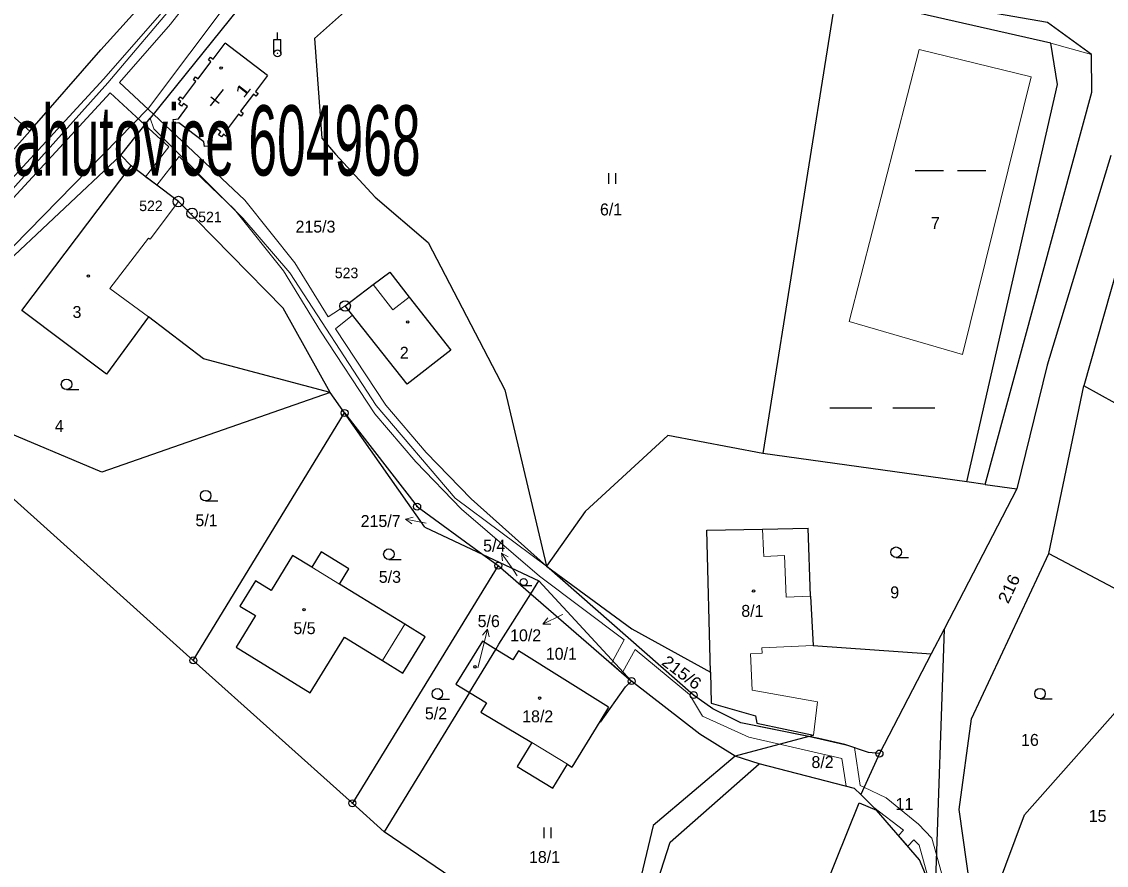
# Model space of a CAD drawing. Extents: x -504006 to -501322, y -1128098 to -1124665.
# Drawn here: x -502824.9 to -502670.2, y -1126824.4 to -1126704.2 of the extents above; entities that cross this region are included whole.
import ezdxf
from ezdxf.enums import TextEntityAlignment as Align

# ---------------------------------------------------------------- set-up
doc = ezdxf.new("R2010")
doc.units = 0
doc.header["$LTSCALE"] = 0.68
for name, color, linetype, lineweight in [('1', 7, 'Continuous', 25), ('13', 7, 'Continuous', 13), ('3', 7, 'Continuous', 25), ('4', 7, 'Continuous', 13), ('5', 7, 'Continuous', 25), ('6', 7, 'Continuous', 25), ('7', 7, 'Continuous', 13), ('8', 7, 'Continuous', 25)]:
    doc.layers.add(name, color=color, linetype=linetype, lineweight=lineweight)
doc.layers.add('2', color=7, linetype='Continuous')

msp = doc.modelspace()

# ---------------------------------------------------------------- linework, layer by layer
at = {"layer": '1'}
for p, q in [((-502774.86, -1126678.46), (-502806.52, -1126717.92)), ((-502813.58, -1126708.19), (-502802.89, -1126696.3)), ((-502708.77, -1126700.27), (-502719.18, -1126765.7)), ((-502678.13, -1126707.24), (-502708.77, -1126700.27)), ((-502678.61, -1126704.28), (-502706.62, -1126699.4)), ((-502776.7, -1126700.81), (-502783.12, -1126706.55)), ((-502672.35, -1126708.85), (-502678.61, -1126704.28)), ((-502783.12, -1126706.55), (-502782.07, -1126720.79)), ((-502823.71, -1126719.75), (-502813.58, -1126708.19)), ((-502797.58, -1126709.49), (-502795.85, -1126707.23)), ((-502789.83, -1126711.86), (-502795.85, -1126707.23)), ((-502677.17, -1126713.1), (-502678.13, -1126707.24)), ((-502798.24, -1126709.62), (-502797.94, -1126709.21)), ((-502797.88, -1126709.89), (-502798.24, -1126709.62)), ((-502797.94, -1126709.21), (-502797.58, -1126709.49)), ((-502672.3, -1126714.21), (-502672.35, -1126708.85)), ((-502799.72, -1126712.31), (-502797.88, -1126709.89)), ((-502801.87, -1126715.14), (-502800.03, -1126712.71)), ((-502800.38, -1126712.44), (-502800.07, -1126712.05)), ((-502800.03, -1126712.71), (-502800.38, -1126712.44)), ((-502800.07, -1126712.05), (-502799.72, -1126712.31)), ((-502789.83, -1126711.86), (-502791.52, -1126714.11)), ((-502791.52, -1126714.11), (-502791.14, -1126714.4)), ((-502791.14, -1126714.4), (-502791.46, -1126714.79)), ((-502690.12, -1126769.75), (-502677.17, -1126713.1)), ((-502687.5, -1126770.11), (-502672.3, -1126714.21)), ((-502802.53, -1126715.27), (-502802.23, -1126714.86)), ((-502802.18, -1126715.54), (-502802.53, -1126715.27)), ((-502802.47, -1126715.92), (-502802.18, -1126715.54)), ((-502802.07, -1126716.22), (-502802.47, -1126715.92)), ((-502802.23, -1126714.86), (-502801.87, -1126715.14)), ((-502801.78, -1126715.84), (-502802.07, -1126716.22)), ((-502801.22, -1126716.26), (-502801.78, -1126715.84)), ((-502791.82, -1126714.52), (-502793.64, -1126716.93)), ((-502791.46, -1126714.79), (-502791.82, -1126714.52)), ((-502802.51, -1126718.02), (-502801.22, -1126716.26)), ((-502793.94, -1126717.34), (-502795.8, -1126719.81)), ((-502793.57, -1126717.62), (-502793.94, -1126717.34)), ((-502793.64, -1126716.93), (-502793.28, -1126717.21)), ((-502793.28, -1126717.21), (-502793.57, -1126717.62)), ((-502810.72, -1126723.17), (-502806.52, -1126717.92)), ((-502803.25, -1126718.11), (-502802.51, -1126718.02)), ((-502803.17, -1126718.69), (-502803.25, -1126718.11)), ((-502802.46, -1126718.59), (-502803.17, -1126718.69)), ((-502798.91, -1126721.27), (-502802.46, -1126718.59)), ((-502826.25, -1126722.68), (-502823.71, -1126719.75)), ((-502797.03, -1126719.45), (-502798.32, -1126721.19)), ((-502796.48, -1126719.87), (-502797.03, -1126719.45)), ((-502796.79, -1126720.29), (-502796.48, -1126719.87)), ((-502796.38, -1126720.59), (-502796.79, -1126720.29)), ((-502796.1, -1126720.21), (-502796.38, -1126720.59)), ((-502795.74, -1126720.48), (-502796.1, -1126720.21)), ((-502795.8, -1126719.81), (-502795.43, -1126720.08)), ((-502795.43, -1126720.08), (-502795.74, -1126720.48)), ((-502798.81, -1126721.95), (-502798.91, -1126721.27)), ((-502798.25, -1126721.9), (-502798.81, -1126721.95)), ((-502798.32, -1126721.19), (-502798.25, -1126721.9)), ((-502782.07, -1126720.79), (-502780.1, -1126723.05)), ((-502663.74, -1126721.77), (-502673.41, -1126756.05)), ((-502836.98, -1126747.85), (-502810.72, -1126723.17)), ((-502809.26, -1126724.71), (-502810.72, -1126723.17)), ((-502780.1, -1126723.05), (-502774.45, -1126729.16)), ((-502669.57, -1126723.24), (-502678.64, -1126753.11)), ((-502824.82, -1126745.34), (-502809.26, -1126724.71)), ((-502802.52, -1126729.8), (-502809.26, -1126724.71)), ((-502787.59, -1126744.98), (-502802.52, -1126729.8)), ((-502774.45, -1126729.16), (-502766.91, -1126735.65)), ((-502766.91, -1126735.65), (-502755.98, -1126756.66)), ((-502774.77, -1126741.64), (-502772.37, -1126739.86)), ((-502772.37, -1126739.86), (-502769.6, -1126743.42)), ((-502778.75, -1126744.69), (-502774.77, -1126741.64)), ((-502769.6, -1126743.42), (-502763.67, -1126750.97)), ((-502812.78, -1126754.4), (-502824.82, -1126745.34)), ((-502780.87, -1126757.03), (-502787.59, -1126744.98)), ((-502769.88, -1126755.81), (-502778.75, -1126744.69)), ((-502806.76, -1126746.24), (-502812.78, -1126754.4)), ((-502798.94, -1126752.2), (-502806.76, -1126746.24)), ((-502763.67, -1126750.97), (-502769.88, -1126755.81)), ((-502780.87, -1126757.03), (-502798.94, -1126752.2)), ((-502678.64, -1126753.11), (-502682.97, -1126770.74)), ((-502813.43, -1126768.36), (-502845.16, -1126755)), ((-502800.39, -1126795.2), (-502845.16, -1126755)), ((-502678.41, -1126779.95), (-502673.41, -1126756.05)), ((-502632.62, -1126778.97), (-502673.41, -1126756.05)), ((-502780.87, -1126757.03), (-502813.43, -1126768.36)), ((-502778.82, -1126759.94), (-502780.87, -1126757.03)), ((-502755.98, -1126756.66), (-502750.05, -1126781.76)), ((-502800.39, -1126795.2), (-502778.82, -1126759.94)), ((-502778.82, -1126759.94), (-502768.48, -1126773.29)), ((-502767.37, -1126776.23), (-502778.82, -1126759.94)), ((-502732.75, -1126763.16), (-502744.53, -1126773.97)), ((-502719.18, -1126765.7), (-502732.75, -1126763.16)), ((-502690.12, -1126769.75), (-502719.18, -1126765.7)), ((-502687.5, -1126770.11), (-502690.12, -1126769.75)), ((-502682.97, -1126770.74), (-502693.34, -1126790.73)), ((-502687.5, -1126770.11), (-502682.97, -1126770.74)), ((-502768.48, -1126773.29), (-502759.11, -1126780.1)), ((-502744.53, -1126773.97), (-502750.05, -1126781.76)), ((-502767.37, -1126776.23), (-502759.11, -1126780.1)), ((-502727.18, -1126776.65), (-502719.22, -1126776.48)), ((-502726.66, -1126796.86), (-502727.18, -1126776.65)), ((-502719.22, -1126776.48), (-502712.72, -1126776.34)), ((-502712.39, -1126786.06), (-502712.72, -1126776.34)), ((-502786.26, -1126780.23), (-502789.3, -1126785.22)), ((-502783.51, -1126781.9), (-502786.26, -1126780.23)), ((-502782.18, -1126779.72), (-502783.51, -1126781.9)), ((-502778.21, -1126782.16), (-502782.18, -1126779.72)), ((-502759.11, -1126780.1), (-502751.13, -1126783.84)), ((-502759.11, -1126780.1), (-502756.91, -1126781.7)), ((-502689.46, -1126803.51), (-502678.41, -1126779.95)), ((-502678.41, -1126779.95), (-502641.75, -1126799.38)), ((-502779.53, -1126784.33), (-502778.21, -1126782.16)), ((-502756.91, -1126781.7), (-502777.71, -1126815.57)), ((-502756.91, -1126781.7), (-502752.29, -1126785.7)), ((-502729.06, -1126800.14), (-502750.05, -1126781.76)), ((-502750.05, -1126781.76), (-502737.86, -1126790.7)), ((-502789.3, -1126785.22), (-502791.53, -1126783.85)), ((-502752.29, -1126785.7), (-502751.13, -1126783.84)), ((-502737.9, -1126798.15), (-502751.13, -1126783.84)), ((-502770.22, -1126790.02), (-502779.53, -1126784.33)), ((-502756.81, -1126792.91), (-502752.29, -1126785.7)), ((-502752.29, -1126785.7), (-502737.9, -1126798.15)), ((-502712.39, -1126786.06), (-502712.03, -1126793.06)), ((-502791.51, -1126788.81), (-502794.29, -1126793.34)), ((-502767.35, -1126791.85), (-502770.22, -1126790.02)), ((-502737.86, -1126790.7), (-502726.66, -1126796.86)), ((-502693.34, -1126790.73), (-502695.19, -1126794.28)), ((-502693.34, -1126790.73), (-502694.72, -1126830.65)), ((-502783.73, -1126799.81), (-502778.84, -1126791.87)), ((-502778.84, -1126791.87), (-502773.4, -1126795.24)), ((-502770.52, -1126797.04), (-502767.35, -1126791.85)), ((-502759.17, -1126792.47), (-502762.94, -1126798.59)), ((-502757.26, -1126793.65), (-502759.17, -1126792.47)), ((-502757.26, -1126793.65), (-502756.81, -1126792.91)), ((-502712.03, -1126793.06), (-502695.19, -1126794.28)), ((-502794.29, -1126793.34), (-502783.73, -1126799.81)), ((-502761.02, -1126799.77), (-502757.26, -1126793.65)), ((-502754.84, -1126795.14), (-502757.26, -1126793.65)), ((-502754.02, -1126793.83), (-502754.84, -1126795.14)), ((-502741.18, -1126801.89), (-502754.02, -1126793.83)), ((-502695.19, -1126794.28), (-502702.56, -1126808.48)), ((-502777.71, -1126815.57), (-502800.39, -1126795.2)), ((-502773.4, -1126795.24), (-502770.52, -1126797.04)), ((-502726.66, -1126796.86), (-502726.54, -1126801.31)), ((-502681.9, -1126817.21), (-502664.13, -1126797.18)), ((-502762.94, -1126798.59), (-502761.02, -1126799.77)), ((-502742.33, -1126804.02), (-502738.77, -1126798.95)), ((-502737.9, -1126798.15), (-502738.77, -1126798.95)), ((-502728.16, -1126805.7), (-502737.9, -1126798.15)), ((-502761.02, -1126799.77), (-502773.2, -1126819.62)), ((-502761.02, -1126799.77), (-502758.61, -1126801.26)), ((-502726.33, -1126802.1), (-502729.06, -1126800.14)), ((-502758.61, -1126801.26), (-502759.41, -1126802.56)), ((-502759.41, -1126802.56), (-502752.12, -1126806.91)), ((-502741.18, -1126801.89), (-502742.44, -1126803.93)), ((-502726.54, -1126801.31), (-502720.23, -1126803.09)), ((-502722.34, -1126804.09), (-502726.33, -1126802.1)), ((-502742.44, -1126803.93), (-502746.41, -1126810.4)), ((-502742.44, -1126803.93), (-502742.33, -1126804.02)), ((-502712.63, -1126806.04), (-502722.34, -1126804.09)), ((-502720.23, -1126803.09), (-502720.04, -1126804.13)), ((-502720.04, -1126804.13), (-502711.99, -1126805.87)), ((-502691.21, -1126816.43), (-502689.46, -1126803.51)), ((-502752.12, -1126806.91), (-502754.21, -1126810.33)), ((-502723.14, -1126808.83), (-502728.16, -1126805.7)), ((-502712.63, -1126806.04), (-502723.14, -1126808.83)), ((-502712.63, -1126806.04), (-502711.99, -1126805.87)), ((-502711.23, -1126806.32), (-502712.63, -1126806.04)), ((-502707.51, -1126807.18), (-502711.23, -1126806.32)), ((-502704.14, -1126808.31), (-502707.51, -1126807.18)), ((-502702.56, -1126808.48), (-502705.24, -1126814.31)), ((-502702.56, -1126808.48), (-502704.14, -1126808.31)), ((-502749.14, -1126813.42), (-502747.05, -1126810.01)), ((-502747.05, -1126810.01), (-502746.41, -1126810.4)), ((-502723.14, -1126808.83), (-502734.84, -1126818.75)), ((-502732.42, -1126821.09), (-502719.72, -1126809.94)), ((-502719.72, -1126809.94), (-502723.14, -1126808.83)), ((-502706.11, -1126813.44), (-502719.72, -1126809.94)), ((-502754.21, -1126810.33), (-502749.14, -1126813.42)), ((-502705.24, -1126814.31), (-502706.11, -1126813.44)), ((-502702.98, -1126816.57), (-502705.24, -1126814.31)), ((-502777.71, -1126815.57), (-502773.2, -1126819.62)), ((-502711.5, -1126830.46), (-502705.45, -1126815.51)), ((-502705.45, -1126815.51), (-502702.98, -1126816.57)), ((-502688.66, -1126834.62), (-502691.21, -1126816.43)), ((-502696.85, -1126823.62), (-502702.98, -1126816.57)), ((-502686.7, -1126830.08), (-502681.9, -1126817.21)), ((-502734.84, -1126818.75), (-502738.33, -1126833.52)), ((-502740.97, -1126841.5), (-502773.2, -1126819.62)), ((-502739.32, -1126842.63), (-502732.42, -1126821.09)), ((-502695.3, -1126827.39), (-502696.85, -1126823.62))]:
    msp.add_line(p, q, dxfattribs=at)
msp.add_lwpolyline([(-502791.53, -1126783.85), (-502793.74, -1126787.47), (-502791.51, -1126788.81)], dxfattribs=at)
at = {"layer": '13'}
for points in [[(-502772.93, -1126666.22), (-502781.43, -1126673.37), (-502789.25, -1126681.94), (-502797.98, -1126694), (-502805.19, -1126703.26), (-502813.13, -1126712.33), (-502839.03, -1126740.37)], [(-502691.6, -1126833.24), (-502694.45, -1126822.9), (-502695.1, -1126820.54), (-502697.01, -1126818.55), (-502701.62, -1126814.8), (-502704.77, -1126813.29), (-502705.32, -1126813.03), (-502706.13, -1126807.64), (-502706.9, -1126807.38), (-502712.67, -1126806.05), (-502722.34, -1126804.09), (-502726.33, -1126802.1), (-502729.06, -1126800.14), (-502750.05, -1126781.76), (-502760.79, -1126772.19), (-502767.18, -1126765.56), (-502772.92, -1126758.84), (-502780.1, -1126747.96), (-502777.69, -1126746.01), (-502778.75, -1126744.69), (-502781.17, -1126746.25), (-502785.9, -1126738.52), (-502793.05, -1126729.6), (-502806.08, -1126717.37), (-502810.91, -1126712.83), (-502803.65, -1126704.54), (-502796.38, -1126695.2)], [(-502837.79, -1126741.97), (-502812.25, -1126714.32), (-502807.29, -1126718.88), (-502803.89, -1126722), (-502807.21, -1126726.26), (-502805.61, -1126727.46), (-502802.42, -1126723.38), (-502794.53, -1126730.96), (-502787.54, -1126739.68), (-502782.27, -1126748.29), (-502774.52, -1126760.04), (-502768.66, -1126766.9), (-502762.17, -1126773.65), (-502751.05, -1126783.18), (-502738.94, -1126792.26), (-502740.57, -1126795.27), (-502740.78, -1126795.66), (-502739.23, -1126797), (-502739.13, -1126796.82), (-502737.41, -1126793.63), (-502729.65, -1126800.05), (-502727.81, -1126803.14), (-502721.21, -1126806.13), (-502716.81, -1126807.15), (-502707.92, -1126809.2), (-502707.33, -1126813.13), (-502706.11, -1126813.44), (-502705.24, -1126814.31), (-502703.37, -1126816.18), (-502699.14, -1126819.4), (-502699.84, -1126820.18), (-502698.52, -1126821.7), (-502697.67, -1126820.76), (-502696.9, -1126821.56), (-502695.3, -1126827.39)]]:
    msp.add_lwpolyline(points, dxfattribs=at)
at = {"layer": '3'}
for p, q in [((-502741.131, -1126727.27), (-502741.131, -1126725.77)), ((-502740.13, -1126727.27), (-502740.13, -1126725.77)), ((-502697.458, -1126725.37), (-502693.438, -1126725.37)), ((-502691.428, -1126725.37), (-502687.408, -1126725.37)), ((-502818.463, -1126756.61), (-502816.713, -1126756.61)), ((-502709.649, -1126759.2), (-502703.649, -1126759.2)), ((-502700.649, -1126759.2), (-502694.649, -1126759.2)), ((-502798.633, -1126772.47), (-502796.883, -1126772.47)), ((-502772.513, -1126780.81), (-502770.763, -1126780.81)), ((-502700.183, -1126780.53), (-502698.433, -1126780.53)), ((-502753.285, -1126784.55), (-502752.113, -1126784.55)), ((-502765.593, -1126800.71), (-502763.843, -1126800.71)), ((-502679.673, -1126800.69), (-502677.923, -1126800.69)), ((-502750.361, -1126820.52), (-502750.361, -1126819.02)), ((-502749.36, -1126820.52), (-502749.36, -1126819.02))]:
    msp.add_line(p, q, dxfattribs=at)
for centre, radius in [((-502818.4629, -1126755.8598), 0.75), ((-502798.6329, -1126771.7198), 0.75), ((-502772.5129, -1126780.0598), 0.75), ((-502700.1829, -1126779.7798), 0.75), ((-502753.2852, -1126784.0474), 0.5025), ((-502765.5929, -1126799.9598), 0.75), ((-502679.6729, -1126799.9398), 0.75)]:
    msp.add_circle(centre, radius, dxfattribs=at)
at = {"layer": '4'}
for p, q in [((-502865.13, -1126683.59), (-502823.71, -1126719.75)), ((-502798.2, -1126695.9), (-502812.6, -1126712.9)), ((-502806.8, -1126716.5), (-502793.8, -1126699.2)), ((-502706.9, -1126746.92), (-502696.89, -1126708.15)), ((-502696.89, -1126708.15), (-502680.94, -1126712.05)), ((-502678.13, -1126707.24), (-502672.35, -1126708.85)), ((-502680.94, -1126712.05), (-502690.74, -1126751.62)), ((-502812.6, -1126712.9), (-502831.2, -1126733.6)), ((-502837.16, -1126747.49), (-502806.8, -1126716.5)), ((-502806.52, -1126717.92), (-502806.01, -1126719.42)), ((-502806.01, -1126719.42), (-502793.35, -1126732.18)), ((-502802.52, -1126729.8), (-502806.56, -1126735.17)), ((-502793.35, -1126732.18), (-502786.62, -1126739.94)), ((-502806.76, -1126735.02), (-502812.27, -1126742.19)), ((-502806.56, -1126735.17), (-502806.76, -1126735.02)), ((-502786.62, -1126739.94), (-502774.34, -1126758.85)), ((-502812.27, -1126742.19), (-502806.76, -1126746.24)), ((-502771.94, -1126745.25), (-502774.77, -1126741.64)), ((-502769.6, -1126743.42), (-502771.94, -1126745.25)), ((-502690.74, -1126751.62), (-502706.9, -1126746.92)), ((-502774.34, -1126758.85), (-502763.07, -1126772.08)), ((-502763.07, -1126772.08), (-502750.05, -1126781.76)), ((-502719.22, -1126776.48), (-502719.09, -1126779.52)), ((-502719.09, -1126779.52), (-502719.06, -1126780.4)), ((-502719.06, -1126780.4), (-502716.1, -1126780.27)), ((-502716.1, -1126780.27), (-502715.86, -1126786.21)), ((-502779.53, -1126784.33), (-502783.51, -1126781.9)), ((-502715.86, -1126786.21), (-502712.39, -1126786.06)), ((-502770.22, -1126790.02), (-502773.4, -1126795.24)), ((-502712.03, -1126793.06), (-502719.33, -1126793.43)), ((-502719.29, -1126794.18), (-502720.96, -1126794.26)), ((-502720.96, -1126794.26), (-502720.7, -1126799.46)), ((-502719.33, -1126793.43), (-502719.29, -1126794.18)), ((-502720.7, -1126799.46), (-502711.38, -1126801.13)), ((-502711.38, -1126801.13), (-502711.99, -1126805.87)), ((-502752.12, -1126806.91), (-502747.05, -1126810.01))]:
    msp.add_line(p, q, dxfattribs=at)
at = {"layer": '5'}
for p, q in [((-502797.927, -1126716.174), (-502796.08, -1126713.81)), ((-502796.719, -1126715.847), (-502797.902, -1126714.923))]:
    msp.add_line(p, q, dxfattribs=at)
for centre in [(-502796.4268, -1126710.7692), (-502815.3568, -1126740.4192), (-502769.8268, -1126746.9592), (-502720.5168, -1126785.2992), (-502784.5968, -1126787.9692), (-502760.2368, -1126796.1192), (-502751.0168, -1126800.5792)]:
    msp.add_circle(centre, 0.175, dxfattribs=at)
at = {"layer": '6'}
for p, q in [((-502788.89, -1126706.686), (-502787.89, -1126706.686)), ((-502788.89, -1126708.686), (-502788.89, -1126706.686)), ((-502788.39, -1126706.686), (-502788.39, -1126705.686)), ((-502787.89, -1126708.686), (-502787.89, -1126706.686))]:
    msp.add_line(p, q, dxfattribs=at)
for radius in [0.5, 0.0303]:
    msp.add_circle((-502788.39, -1126708.6876), radius, dxfattribs=at)
at = {"layer": '7'}
for p, q in [((-502770.116, -1126775.077), (-502769.228, -1126775.76)), ((-502756.471, -1126779.902), (-502756.307, -1126781.009)), ((-502750.547, -1126790.046), (-502749.428, -1126790.057)), ((-502758.454, -1126790.758), (-502759.182, -1126791.609))]:
    msp.add_line(p, q, dxfattribs=at)
for points in [[(-502767.17, -1126775.65), (-502770.116, -1126775.077), (-502769.037, -1126774.777)], [(-502754.21, -1126783.14), (-502754.75, -1126782.36), (-502756.471, -1126779.902), (-502755.487, -1126780.435)], [(-502747.72, -1126788.67), (-502747.85, -1126788.73), (-502750.547, -1126790.046), (-502749.867, -1126789.156)], [(-502759.83, -1126796.25), (-502759.18, -1126793.67), (-502758.454, -1126790.758), (-502758.21, -1126791.851)]]:
    msp.add_lwpolyline(points, dxfattribs=at)
at = {"layer": '8'}
for centre, radius in [((-502802.52, -1126729.7998), 0.75), ((-502802.52, -1126729.7998), 0.03), ((-502800.57, -1126731.4898), 0.75), ((-502800.57, -1126731.4898), 0.03), ((-502778.75, -1126744.6898), 0.75), ((-502778.75, -1126744.6898), 0.03), ((-502778.82, -1126759.9399), 0.5), ((-502778.82, -1126759.9399), 0.0303), ((-502768.48, -1126773.2899), 0.5), ((-502768.48, -1126773.2899), 0.0303), ((-502756.91, -1126781.6999), 0.5), ((-502756.91, -1126781.6999), 0.0303), ((-502800.39, -1126795.1999), 0.5), ((-502800.39, -1126795.1999), 0.0303), ((-502737.9, -1126798.1499), 0.5), ((-502737.9, -1126798.1499), 0.0303), ((-502729.06, -1126800.1399), 0.5), ((-502729.06, -1126800.1399), 0.0303), ((-502702.56, -1126808.4799), 0.5), ((-502702.56, -1126808.4799), 0.0303), ((-502777.71, -1126815.5699), 0.5), ((-502777.71, -1126815.5699), 0.0303)]:
    msp.add_circle(centre, radius, dxfattribs=at)

# ---------------------------------------------------------------- texts
at = {"layer": '2'}
for s, rotation, width, p in [('1', 52, 1.5, (-502792.6567, -1126714.4348)), ('216', 65, 1.1, (-502683.3288, -1126785.3467)), ('215/6', 323, 1.1, (-502731.2645, -1126797.5951))]:
    msp.add_text(s, height=1.7, rotation=rotation, dxfattribs=dict(at, width=width)).set_placement(p, align=Align.CENTER)
for s, p in [('6/1', (-502740.83, -1126731.775)), ('215/3', (-502782.97, -1126734.225)), ('7', (-502694.59, -1126733.715)), ('3', (-502816.98, -1126746.395)), ('2', (-502770.32, -1126752.205)), ('4', (-502819.5, -1126762.635)), ('5/1', (-502798.51, -1126776.075)), ('5/4', (-502757.49, -1126779.705)), ('5/3', (-502772.36, -1126784.145)), ('9', (-502700.39, -1126786.355)), ('5/6', (-502758.27, -1126790.455)), ('8/1', (-502720.68, -1126788.995)), ('5/5', (-502784.54, -1126791.455)), ('10/2', (-502753.009, -1126792.475)), ('10/1', (-502747.919, -1126795.105)), ('5/2', (-502765.79, -1126803.605)), ('18/2', (-502751.289, -1126804.025)), ('16', (-502681.109, -1126807.385)), ('8/2', (-502710.68, -1126810.545)), ('11', (-502698.999, -1126816.525)), ('15', (-502671.459, -1126818.215)), ('18/1', (-502750.319, -1126824.075))]:
    msp.add_text(s, height=1.7, dxfattribs=at).set_placement(p, align=Align.CENTER)
msp.add_text('215/7', height=1.7, dxfattribs=at).set_placement((-502770.84, -1126776.192), align=Align.RIGHT)
at = {"layer": '7', "width": 0.55}
msp.add_text('Blahutovice 604968', height=10, dxfattribs=at).set_placement((-502800.3, -1126726.093), align=Align.CENTER)
at = {"layer": '8'}
for s, p in [('522', (-502804.759, -1126731.165)), ('521', (-502796.349, -1126732.747)), ('523', (-502776.869, -1126740.725))]:
    msp.add_text(s, height=1.5, dxfattribs=at).set_placement(p, align=Align.RIGHT)

doc.saveas('drawing.dxf')
